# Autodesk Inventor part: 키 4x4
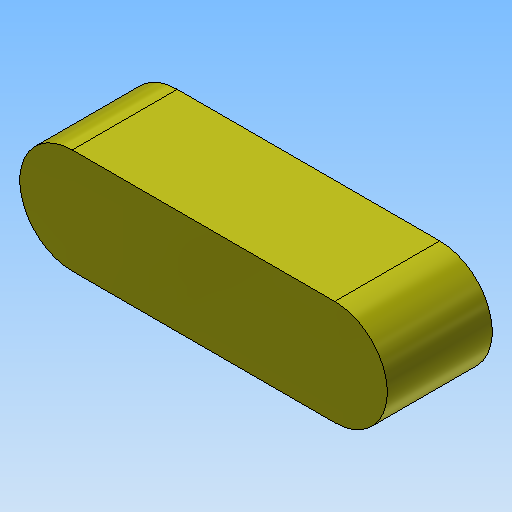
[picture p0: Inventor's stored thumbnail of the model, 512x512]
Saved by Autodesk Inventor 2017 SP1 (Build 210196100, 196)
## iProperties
Created: 2018-09
Part Number: 키 4x4
Document SubType Name: Modeling
Density: 1 g/cm^3
Material: 강철, 연강
Appearance: 노란색
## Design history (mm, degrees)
sketch "스케치1"
  geometry: L1 (-5, -2)-(5, -2); L2 (5, 2)-(-5, 2); A1 r 2 centre (5, 0) between (5, -2) and (5, 2); A2 r 2 centre (-5, 0) between (-5, 2) and (-5, -2); 2 further points
  constraints: 4 end point, 4 point on circle, 4 tangent, 2 centre point, 1 horizontal, 1 horizontal alignment, 1 midpoint, 1 parallel, 1 vertical alignment
  dimensions: "d0" = 4 distance between parallel lines of L1 L2; "d1" = 14 dimension on A1 A2
extrude "돌출1" new body sketch "스케치1" stored distance "d2" = 4; taper "d3" = 0 deg
node "솔리드1"
